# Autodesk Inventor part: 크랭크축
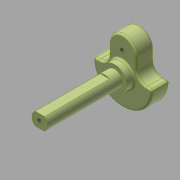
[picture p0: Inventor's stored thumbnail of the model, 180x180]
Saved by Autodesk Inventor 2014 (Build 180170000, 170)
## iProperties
Created: 2018-01
Part Number: 크랭크축
Material: 강철, 탄소
Document SubType Name: Modeling
Designer: mduedu
Density: 1 g/cm^3
Appearance: 아연 크롬산색 2
Author: mduedu
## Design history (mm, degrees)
sketch "스케치1"
  geometry: L1 (-15, 0)-(15, 0); L2 (-7, 0)-(7, 0); L3 (7, 0)-(7, 10); L4 (-7, 10)-(-7, 0); A1 r 15 centre (0, 0) between (-15, 0) and (15, 0); A2 r 7 centre (0, 10) between (7, 10) and (-7, 10); 3 further points
  constraints: 8 end point, 4 point on circle, 3 coincident, 2 centre point, 2 horizontal, 2 midpoint, 2 tangent, 1 parallel, 1 perpendicular, 1 point on line
  dimensions: "d0" = 30 diameter of A1; "d1" = 17 dimension on A2 L1; "d2" = 7 radius of A2
extrude "돌출1" new body sketch "스케치1" distance "d4" = 9; taper "d5" = 0 deg
sketch "스케치2"
  geometry: C1 r 6 at (0, 0); 1 further point
  constraints: 1 centre point, 1 coincident
  dimensions: "d6" = 12 diameter of C1
extrude "돌출2" join sketch "스케치2" distance "d7" = 4; taper "d8" = 0 deg
sketch "스케치3"
  geometry: C1 r 4 at (0, 0); 1 further point
  constraints: 1 centre point, 1 coincident
  dimensions: "d9" = 8 diameter of C1
extrude "돌출3" join sketch "스케치3" distance "d10" = 38; taper "d11" = 0 deg
sketch "스케치4"
  geometry: L1 (-2.332, 3.25)-(2.332, 3.25); L2 (-2.332, -3.25)-(2.332, -3.25); A1 r 4 centre (0, 0) between (-2.332, 3.25) and (2.332, 3.25) reference; A2 r 4 centre (0, 0) between (2.332, 3.25) and (-2.332, 3.25); A3 r 4 centre (0, 0) between (-2.332, -3.25) and (2.332, -3.25); 1 further point
  constraints: 8 point on circle, 4 end point, 2 centre point, 2 coincident, 2 parallel, 1 horizontal
  dimensions: "d12" = 6.5 distance between parallel lines of L2 L1
extrude "돌출4" cut sketch "스케치4" distance "d13" = 33; taper "d14" = 0 deg
fillet "모깎기1" dims "d15" = 5
fillet "모깎기2" dims "d16" = 1
fillet "모깎기3" dims "d17" = 1
fillet "모깎기4" dims "d18" = 1
sketch "스케치5"
  geometry: 1 further point
  constraints: 1 other
hole "구멍1" sketch "스케치5" at (0, 10) diameter "d19" = 2.459; stored, may be unused: countersink angle "d23" = 90 deg, drill point angle "d25" = 120 deg; dims "d20" = 10, "d21" = 4, "d22" = 2, "d24" = 11.5
sketch "스케치6"
  geometry: 1 further point
  constraints: 1 other
hole "구멍2" sketch "스케치6" at (0, 0) diameter "d26" = 2.459; stored, may be unused: countersink angle "d30" = 90 deg, drill point angle "d32" = 120 deg; dims "d27" = 12.7, "d28" = 4, "d29" = 2, "d31" = 14.2
node "솔리드1"
node "투영된 루프1"
